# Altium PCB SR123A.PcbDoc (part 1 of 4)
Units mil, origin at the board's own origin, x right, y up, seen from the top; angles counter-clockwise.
Board outline 5500 x 3200 mil, 4 copper layers (Top Layer, Signal Layer 1, Signal Layer 2, Bottom Layer), stack 64.312 mil thick; 295 components, 105 nets, 659 pads, 1365 vias.
Unrouted connection lines stored in the file: 735.
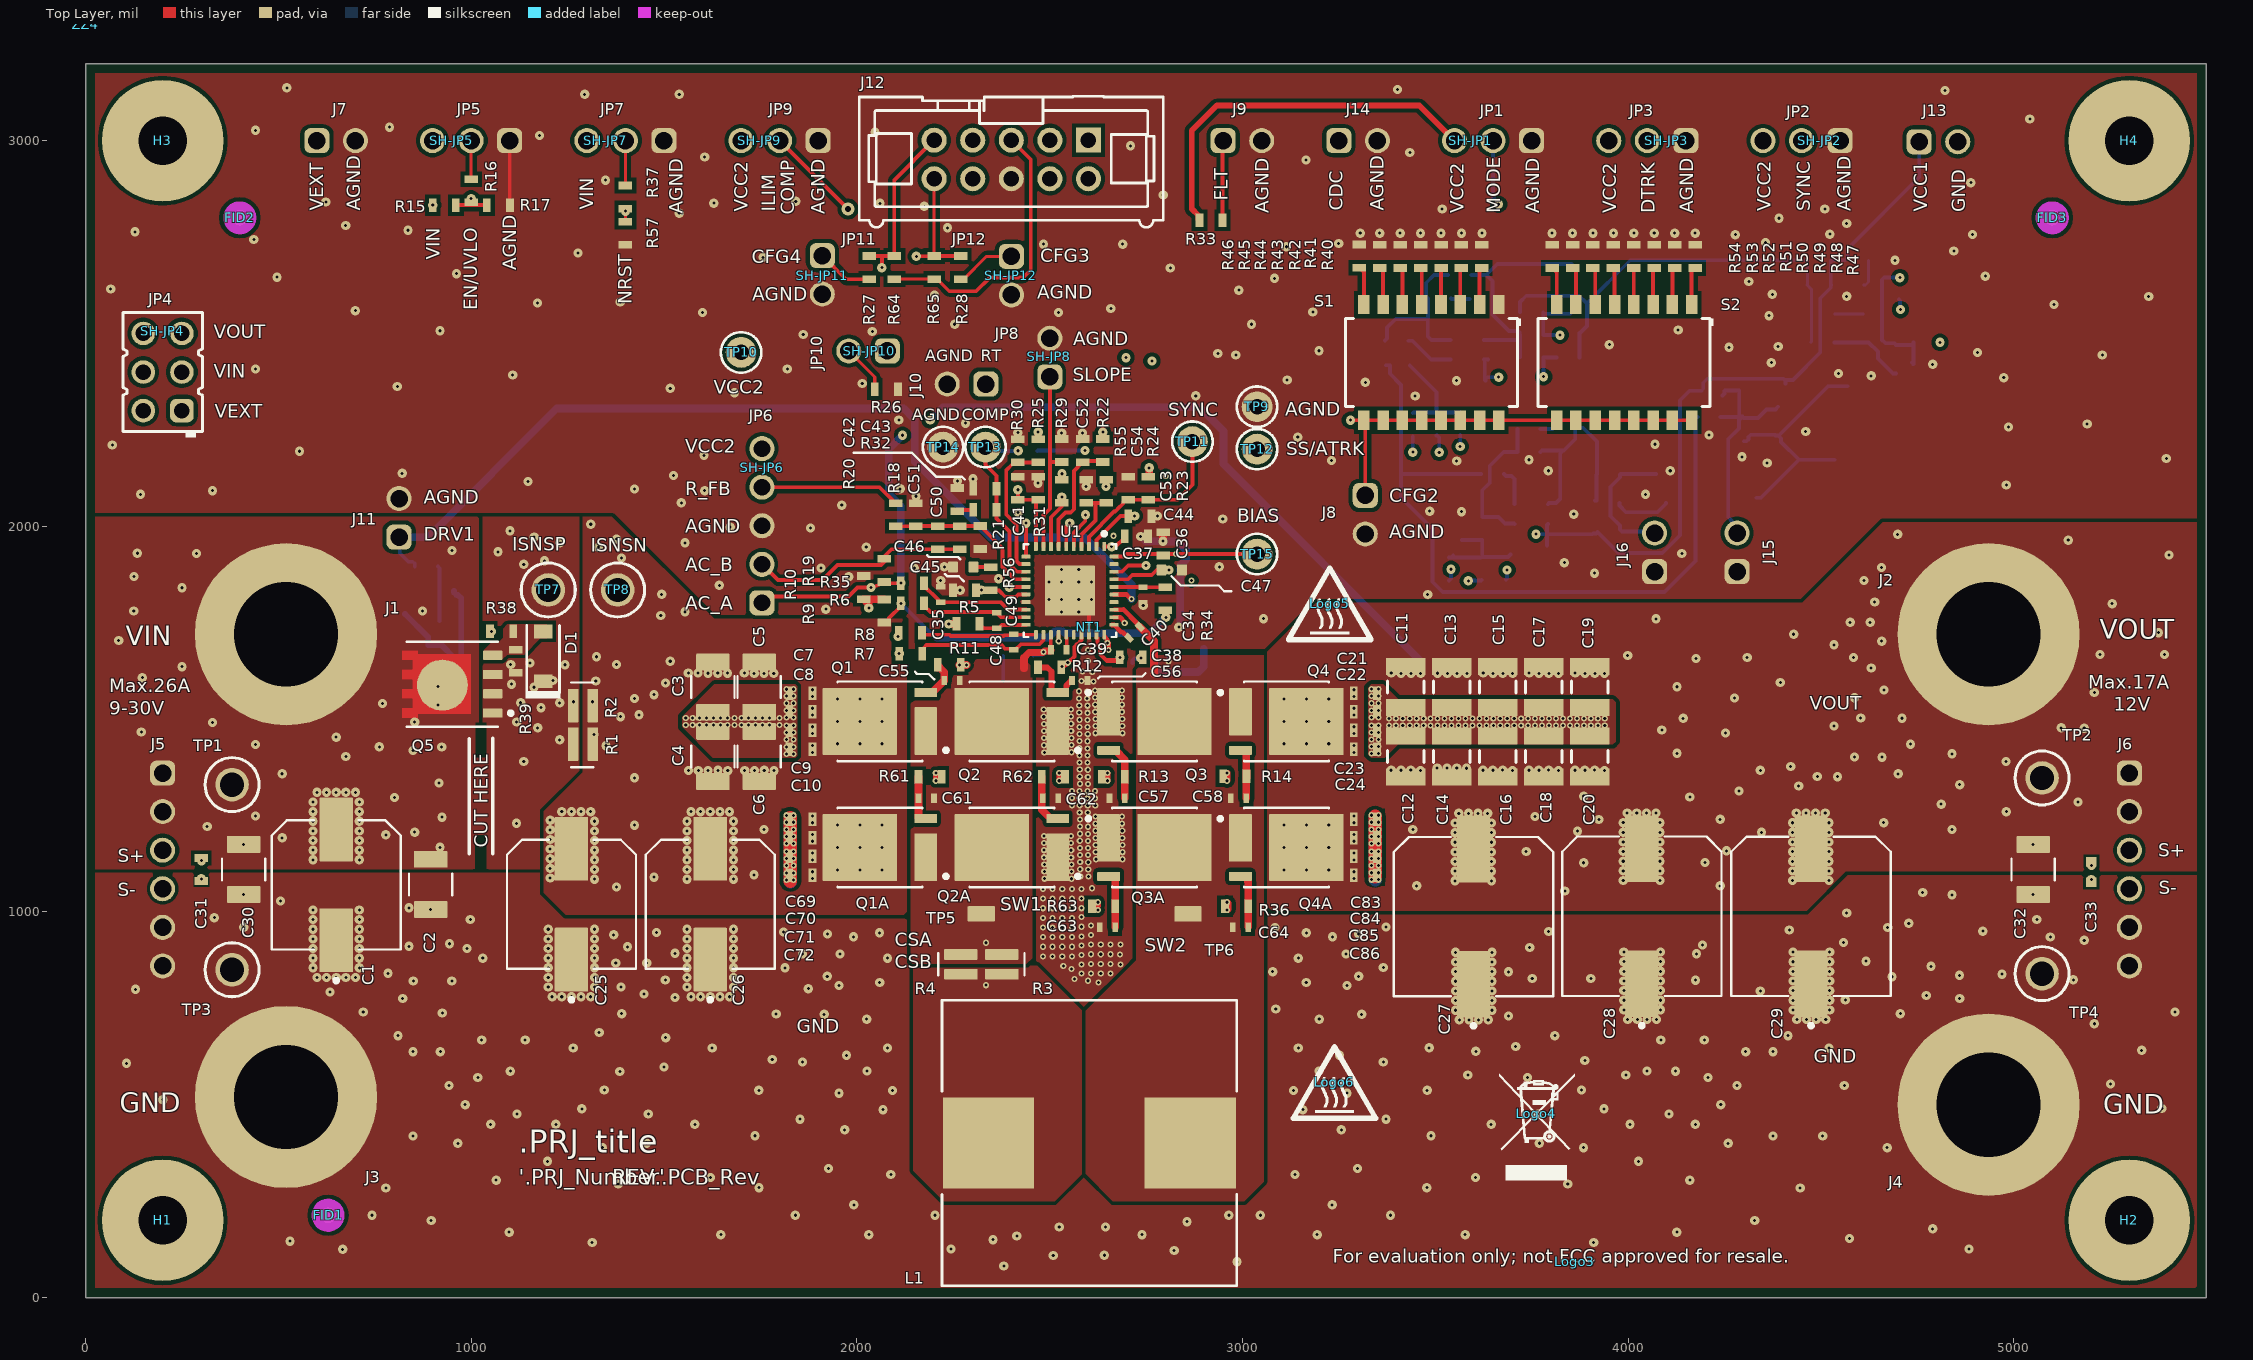
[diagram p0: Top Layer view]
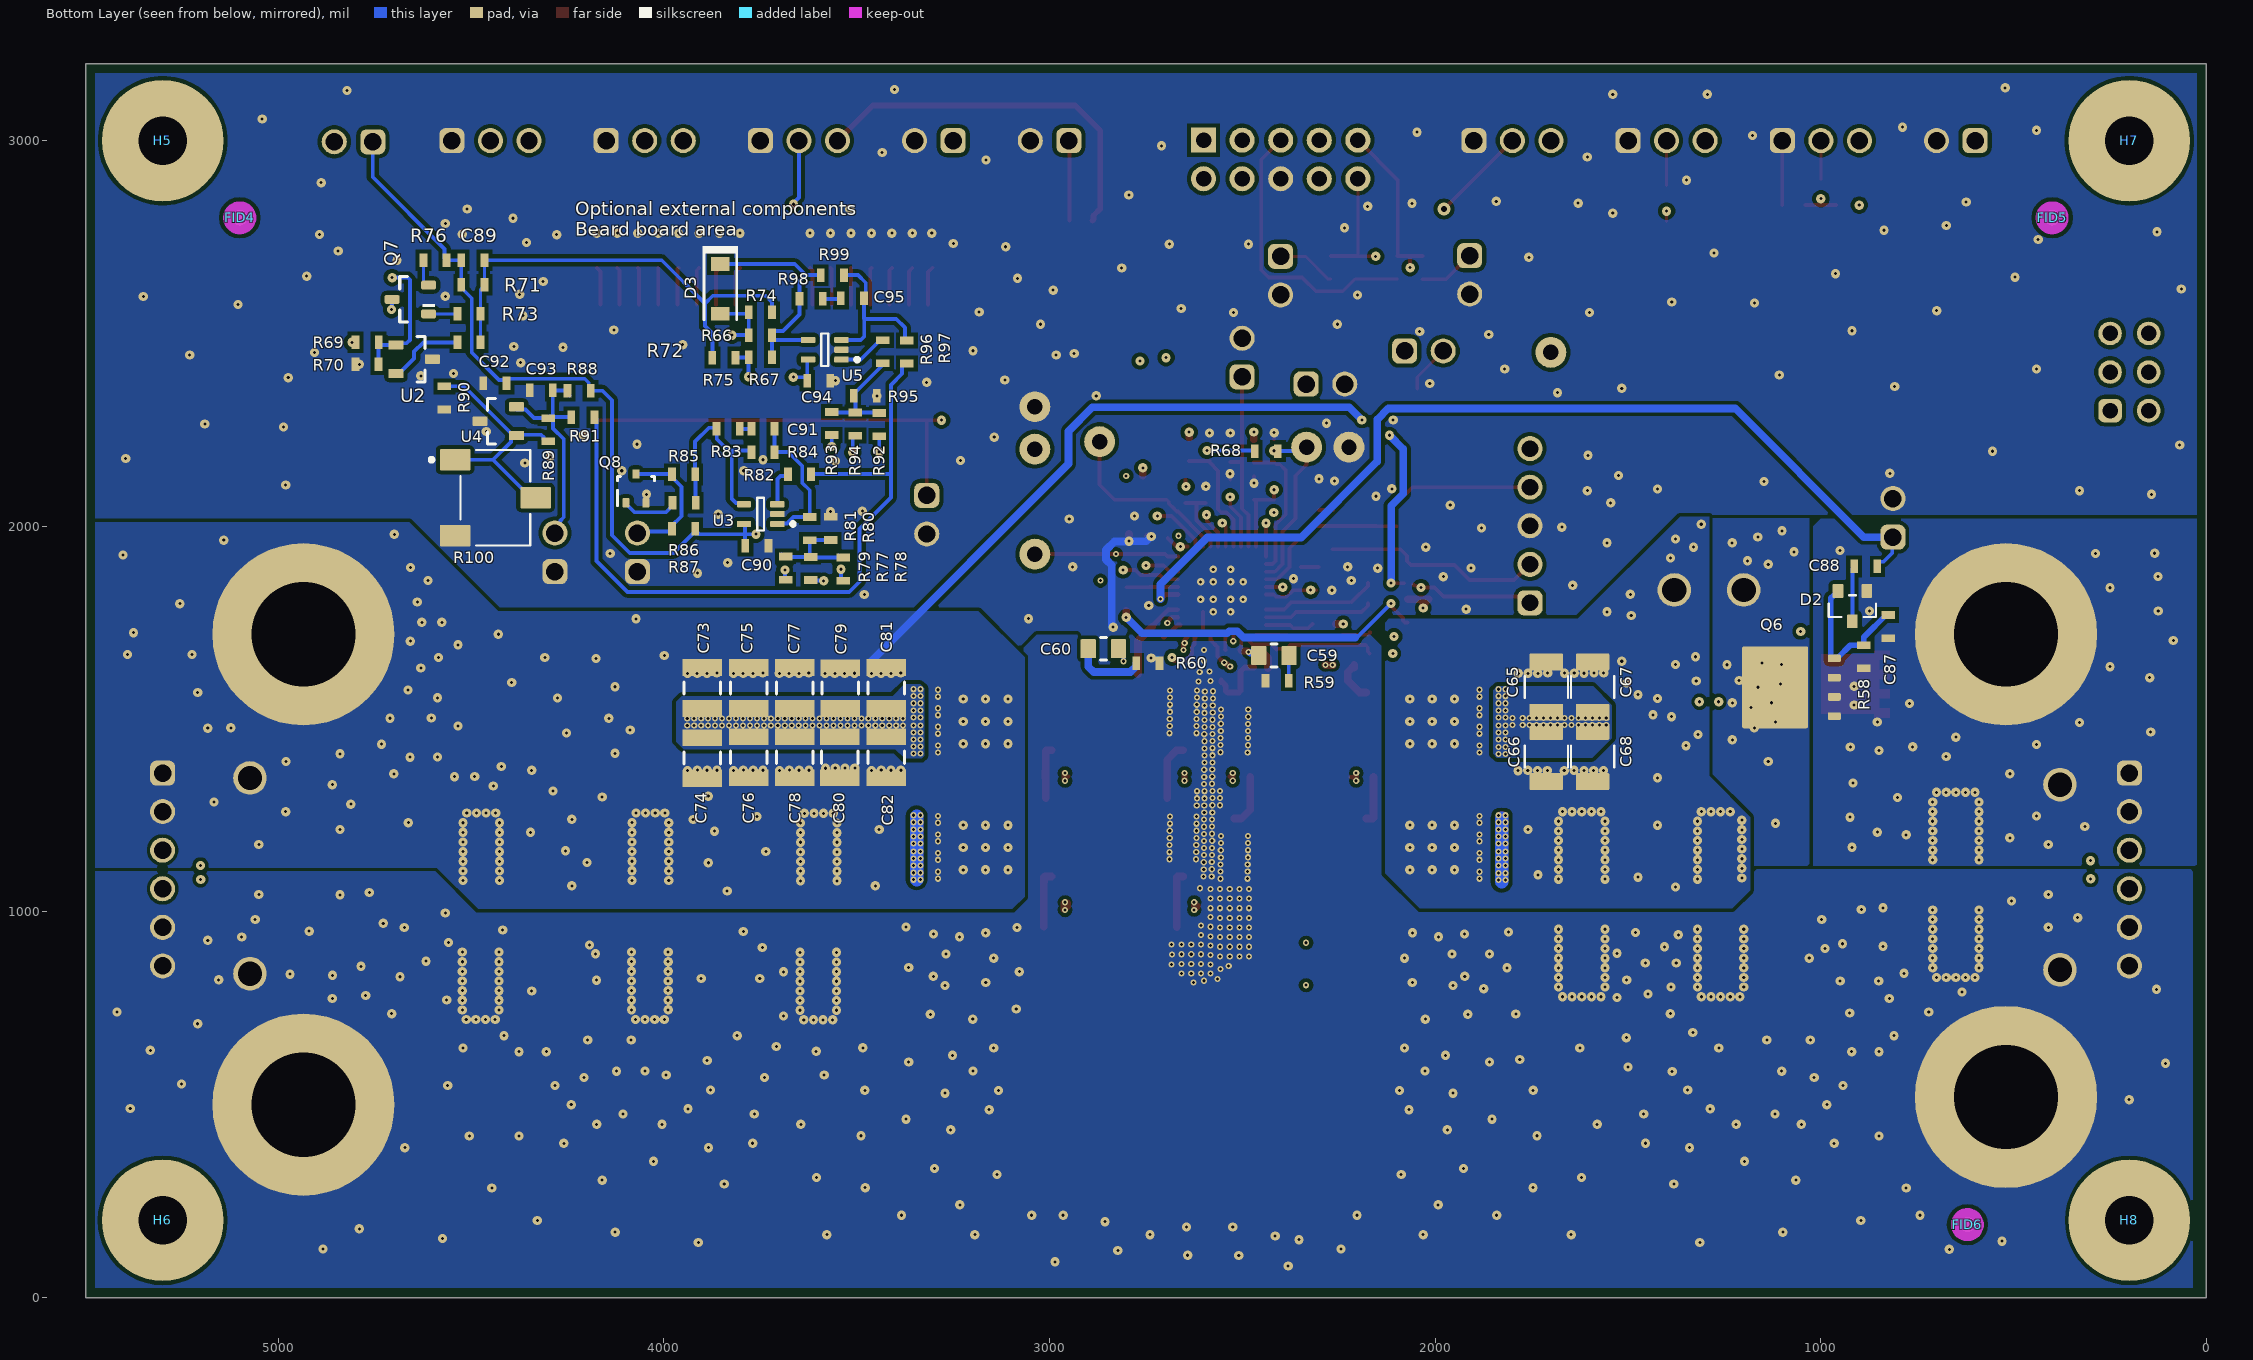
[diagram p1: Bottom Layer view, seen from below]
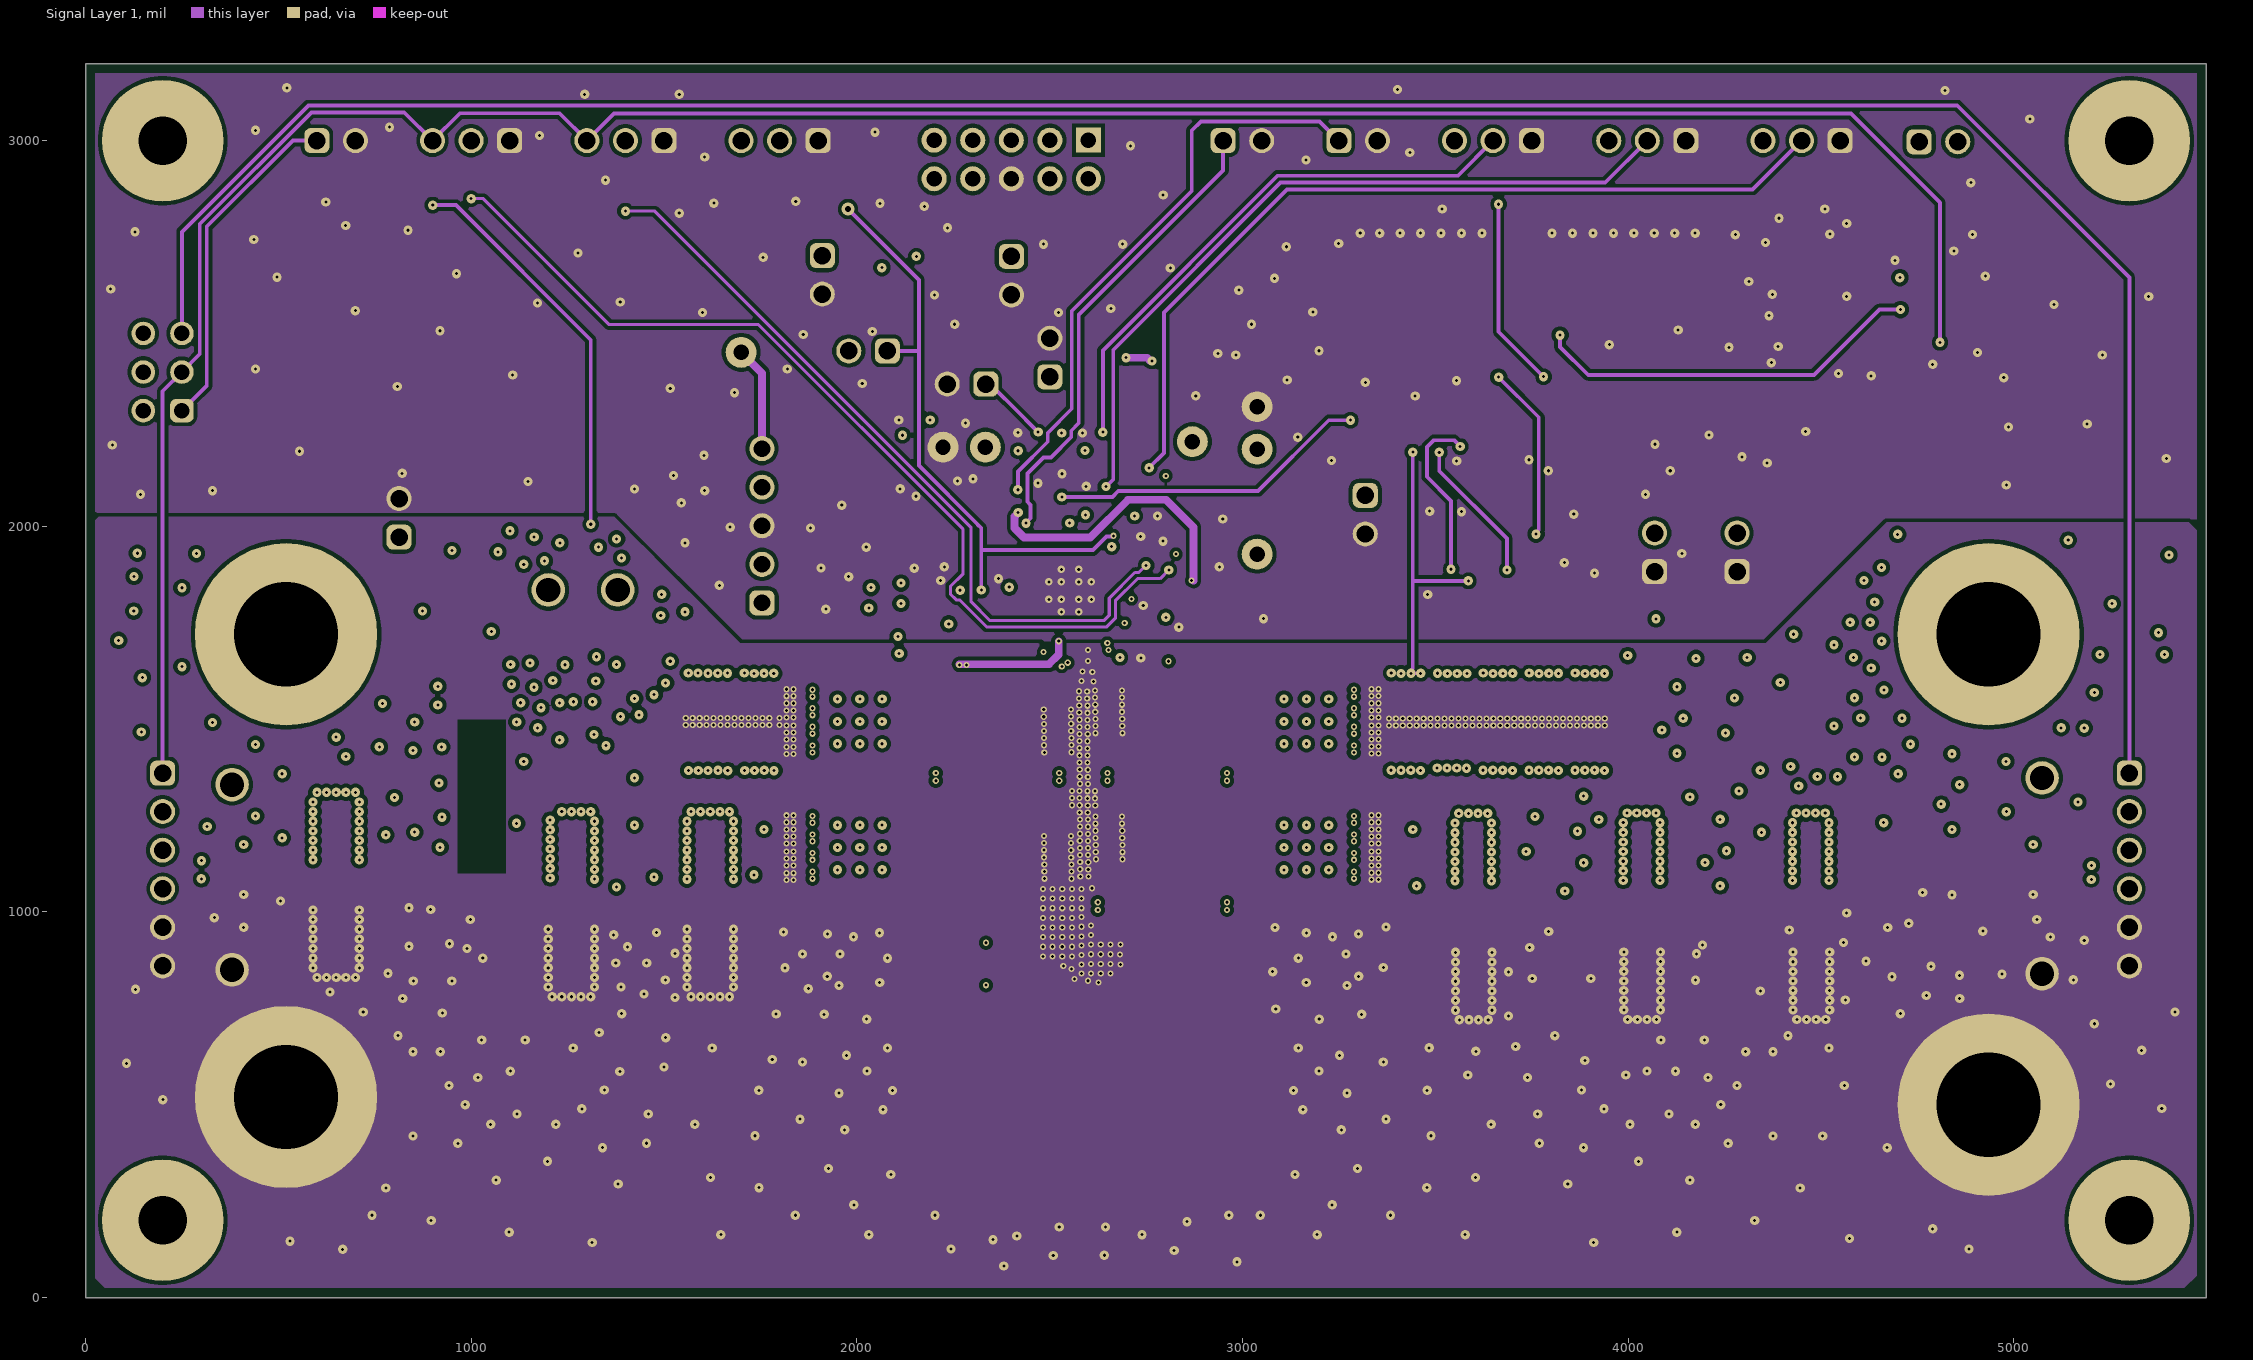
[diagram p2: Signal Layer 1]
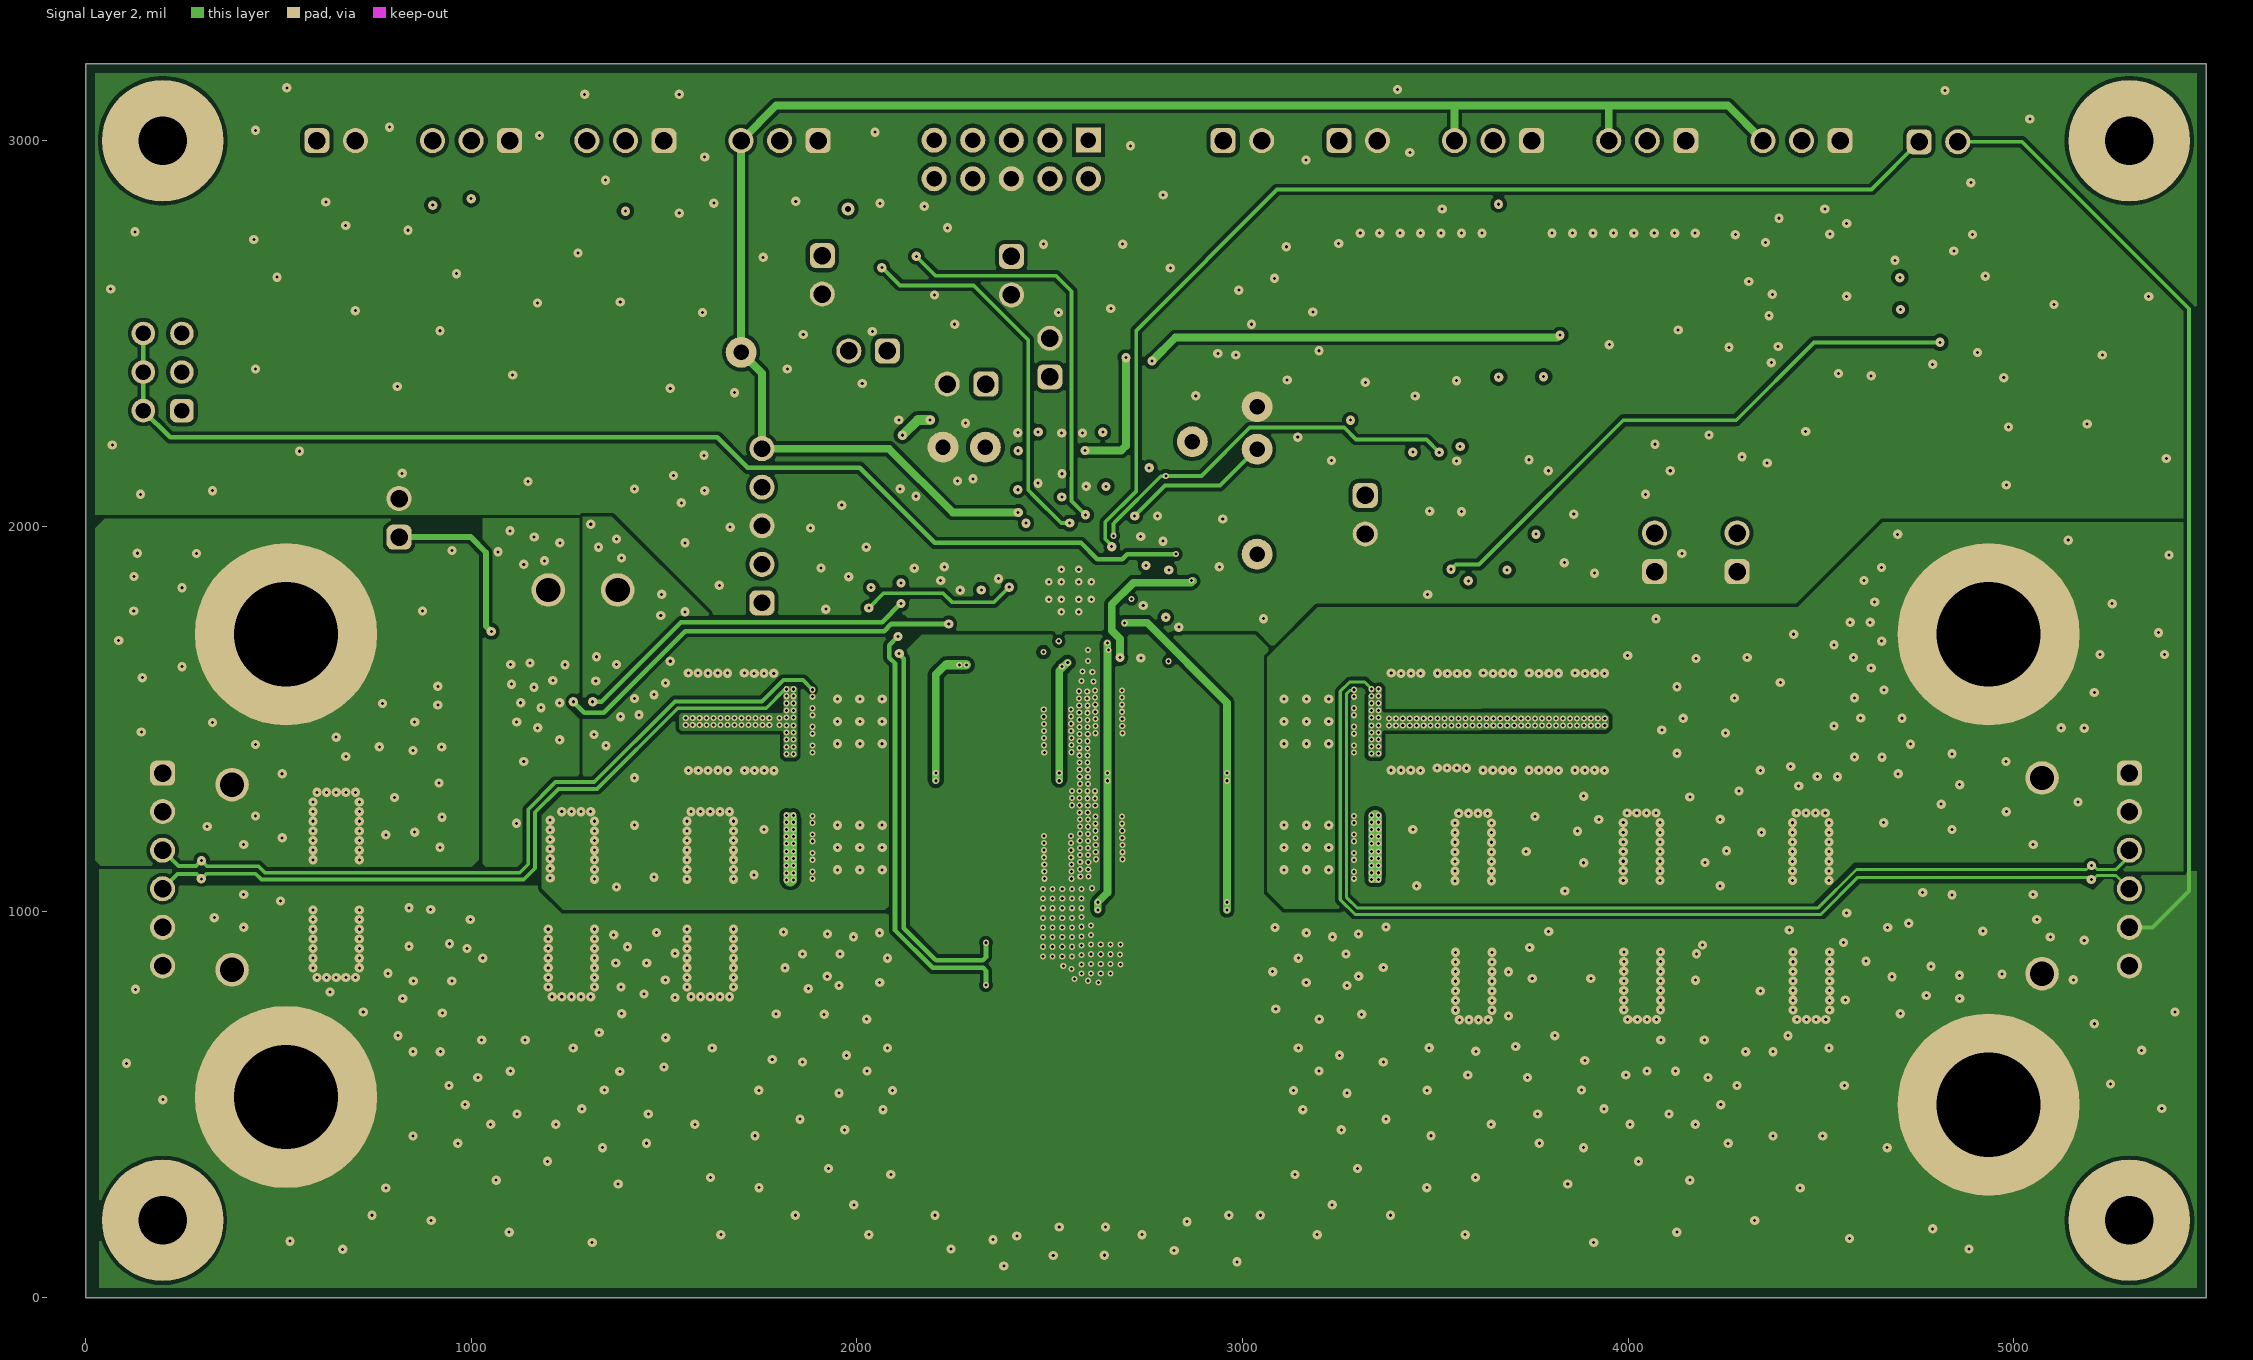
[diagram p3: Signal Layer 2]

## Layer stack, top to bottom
Top Solder: solder mask 0.4, Solder Resist, Dk 3.5
Top Layer: signal copper 2.8
Dielectric 1: prepreg 8, FR-4 High Tg, Dk 4.2
Signal Layer 1: signal copper 2.7559
Dielectric 2: core 37.2, FR-4 High Tg, Dk 4.2
Signal Layer 2: signal copper 2.7559
Dielectric 3: prepreg 8, FR-4 High Tg, Dk 4.2
Bottom Layer: signal copper 2.8
Bottom Solder: solder mask 0.4, Solder Resist, Dk 3.5

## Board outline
5500,0 5500,3200 0,3200 0,0

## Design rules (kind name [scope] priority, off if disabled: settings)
AcuteAngle [All] p1: minimum=4.50000000000000E+0001 checktracksonly=TRUE
AssemblyTestPointUsage [All] p1: valid=2
BoardOutlineClearance BoardOutlineClearance_MountingHoles [OnCopper and InComponentClass('Mounting Holes')] p1: gap=39.37 ignorepadtopadclearanceinfootprint=FALSE
BoardOutlineClearance BoardOutlineClearance_Poly [OnCopper and IsPoly] p2: gap=25 ignorepadtopadclearanceinfootprint=FALSE
BoardOutlineClearance [OnCopper and Not InComponentClass('Logo') and not InComponentClass('FiducialMark') and not InRegion(1000,500,4000,800) and not InPoly] p3: gap=40 ignorepadtopadclearanceinfootprint=FALSE
Clearance Clearance_Keepouts [((IsTrack Or IsArc) And Not InPoly) And IsFree and IsKeepOut vs ((IsTrack Or IsArc) And Not InPoly) And IsFree and IsKeepOut] p1: gap=0 ignorepadtopadclearanceinfootprint=FALSE
Clearance Clearance_Poly [InPolygon] p2: gap=10 ignorepadtopadclearanceinfootprint=TRUE
Clearance Clearance_FiducialMark [IsKeepOut and InComponentClass('FiducialMark') vs IsPad and InComponentClass('FiducialMark')] p3: gap=0 ignorepadtopadclearanceinfootprint=FALSE
Clearance [All] p4: gap=7.87 ignorepadtopadclearanceinfootprint=TRUE
ComponentClearance ComponentClearance_TP [InComponent('TP15')or InComponent('TP16')or InComponent('TP17')or InComponent('TP18')or InComponent('TP23')or InComponent('TP24')or InComponent('TP12')or InComponent('TP13')or InComponent('TP21')or InComponent('TP22') or InComponent('R100')] p1: gap=10 collisioncheckmode=3 verticalgap=0 showdistances=FALSE
ComponentClearance ComponentClearance_NT [InComponent('NT1') or InComponent('NT2')] p2: gap=-1 collisioncheckmode=3 verticalgap=0 showdistances=FALSE
ComponentClearance ComponentClearance_MountingHoles_FiducialMarks [InComponentClass('Mounting Holes') vs InComponentClass('FiducialMark')] p3: gap=50 collisioncheckmode=3 verticalgap=10 showdistances=FALSE
ComponentClearance ComponentClearance_Shunt [InComponentClass('Header') vs InComponent('SH-JP1') or InComponent('SH-JP2') or InComponent('SH-JP3') or InComponent('SH-JP4') or InComponent('SH-JP5') or InComponent('SH-JP6') or InComponent('SH-JP7') or InComponent('SH-JP8') or InComponent('SH-JP9') or InComponent('SH-JP10') or InComponent('SH-JP11') or InComponent('SH-JP12')] p4: gap=-1 collisioncheckmode=3 verticalgap=0 showdistances=FALSE
ComponentClearance ComponentClearance_Logo [InComponentClass('Logo')] p5: gap=20 collisioncheckmode=3 verticalgap=10 showdistances=FALSE
ComponentClearance ComponentClearance_ScrewToNut [(HasFootprint('NY PMS 440 0025 PH')) vs (HasFootprint('Keystone_1902C'))] p6: gap=5 collisioncheckmode=3 verticalgap=10 showdistances=FALSE
ComponentClearance ComponentClearance_MountingHoles [InComponentClass('Mounting Holes')] p7: gap=100 collisioncheckmode=3 verticalgap=100000 showdistances=FALSE
ComponentClearance ComponentClearance_SmallPassives [HasFootprint('0201*') or HasFootprint('0402*') or HasFootprint('0508') or HasFootprint('0603*') or HasFootprint('0612') or HasFootprint('0805*') or HasFootprint('0815*') or HasFootprint('0830*') or HasFootprint('1206*') or HasFootprint('1210*') or HasFootprint('1808*') or HasFootprint('1812*') or HasFootprint('1825*') or HasFootprint('2010*') or HasFootprint('2220*') or HasFootprint('2225*') or HasFootprint('2512*') or HasFootprint('2728*') or HasFootprint('3518*') vs HasFootprint('0201*') or HasFootprint('0402*') or HasFootprint('0508') or HasFootprint('0603*') or HasFootprint('0612') or HasFootprint('0805*') or HasFootprint('0815*') or HasFootprint('0830*') or HasFootprint('1206*') or HasFootprint('1210*') or HasFootprint('1808*') or HasFootprint('1812*') or HasFootprint('1825*') or HasFootprint('2010*') or HasFootprint('2220*') or HasFootprint('2225*') or HasFootprint('2512*') or HasFootprint('2728*') or HasFootprint('3518*')] p8: gap=10 collisioncheckmode=3 verticalgap=10 showdistances=FALSE
ComponentClearance ComponentClearance_THtoSMT [IsThruComponent vs IsSMTComponent] p9: gap=30 collisioncheckmode=3 verticalgap=30 showdistances=FALSE
ComponentClearance ComponentClearance_THtoTH [IsThruComponent vs IsThruComponent] p10: gap=20 collisioncheckmode=3 verticalgap=30 showdistances=FALSE
DiffPairsRouting [All] p1: maxlimit=100 minlimit=10 mostfreqgap=10 toplayer_minwidth=15 toplayer_maxwidth=15 toplayer_prefwidth=15 midlayer1_minwidth=15 midlayer1_maxwidth=15 midlayer1_prefwidth=15 midlayer2_minwidth=15 midlayer2_maxwidth=15 midlayer2_prefwidth=15 bottomlayer_minwidth=15 bottomlayer_maxwidth=15 bottomlayer_prefwidth=15 maxuncoupledlength=1000
FabricationTestPointUsage TestPointUsage [All] p1: valid=2 allowmultiple=FALSE
FabricationTestpoint Testpoint [All] p1: side=3 testpointundercomponent=TRUE minsize=40 maxsize=100 preferedsize=60 minholesize=0 maxholesize=40 preferedholesize=32 testpointgrid=1 allowsidetop=TRUE allowsidebottom=TRUE usegrid=TRUE gridtolerance=0.01
FanoutControl Fanout_LCC [IsLCC] p1: bgadir=Out bgaviamode=Centered fanoutstyle=Auto fanoutdirection=Alternating viagrid=1 // Fanout_LCC (Default Rule)
FanoutControl Fanout_BGA [IsBGA] p2: bgadir=Out bgaviamode=Centered fanoutstyle=Auto fanoutdirection=Alternating viagrid=1 // Fanout_BGA (Default Rule)
FanoutControl Fanout_Default [All] p4: bgadir=Out bgaviamode=Centered fanoutstyle=Auto fanoutdirection=Alternating viagrid=1 // Fanout_Default (Default Rule)
FanoutControl Fanout_Small [(CompPinCount < 5)] p5: bgadir=Out bgaviamode=Centered fanoutstyle=Auto fanoutdirection=OutThenIn viagrid=1 // Fanout_Small (Default Rule)
HoleSize [All] p1: absolutevalues=TRUE maxlimit=275 minlimit=7.87 maxpercent=80.000 minpercent=20.000
MinimumAnnularRing MinimumAnnularRing_QFN_Room [WithinRoom('QFN_Room')] p1: minimumring=5.9
MinimumAnnularRing MinimumAnnularRing_ThermalPadVias [IsVia and InAnyComponent] p2: minimumring=5.91
MinimumAnnularRing [All] p3: minimumring=4
MinimumSolderMaskSliver MinimumSolderMaskSliver_Logo [InComponentClass('Logo') vs InComponentClass('Logo')] p1: minsoldermaskwidth=0.7
MinimumSolderMaskSliver [All] p2: minsoldermaskwidth=3.94
PlaneConnect [All] p1: planeconnectstyle=Relief reliefexpansion=10 reliefentries=4 reliefconductorwidth=10 reliefairgap=10
PolygonConnect [All] p1: connectstyle=Direct reliefconductorwidth=10 reliefentries=4 polygonreliefangle="90 Angle" airgapwidth=10
RoomDefinition QFN_Room [False] p1: confinementstyle=ConfineIn formatcopy=TRUE lockcomponents=FALSE outline 2447.29,1945.95 2657.01,1945.95 2657.01,1733.12 2447.29,1733.12
RoutingVias RoutingVias_QFN_Room [WithinRoom('QFN_Room')] p1: holewidth=28 width=50 viastyle="Through Hole" minholewidth=7.87 minwidth=19.68 maxholewidth=28 maxwidth=50
RoutingVias ThermalPadVias [IsVia and InAnyComponent] p2: holewidth=7.87 width=19.68 viastyle="Through Hole" minholewidth=7.87 minwidth=19.68 maxholewidth=12.99 maxwidth=23.62
RoutingVias [All] p3: holewidth=16 width=34 viastyle="Through Hole" minholewidth=7.87 minwidth=16 maxholewidth=40 maxwidth=65
SilkToBoardRegionClearance [Not ((IsComment or IsDesignator) And (Hide <> 'False')) and not InRegion(1000,500,4000,800)] p1:
SilkToSilkClearance SilkToSilkClearance_Pb-FreeLogo [(HasFootprint('Pb-Free_Overlay_Medium') OR HasFootprint('Pb-Free_Overlay_Small')) vs (HasFootprint('Pb-Free_Overlay_Medium') OR HasFootprint('Pb-Free_Overlay_Small'))] p1: silktosilkclearance=0
SilkToSilkClearance [All] p2: silktosilkclearance=3.94
SilkToSolderMaskClearance SilkToComponentPadClearance [(IsPad or IsFill or IsRegion) and InAnycomponent] p1: minsilkscreentomaskgap=5 clearancetoexposedcopper=TRUE
SilkToSolderMaskClearance "Silk to Solder Mask Opening" [All] p2: minsilkscreentomaskgap=3.94 clearancetoexposedcopper=FALSE
SolderMaskExpansion [All] p1: expansion=1.97 istentingtop=FALSE
SupplyNets "Schematic Supply Nets_3" [InNet('GND')] p1: voltage=0.000
SupplyNets "Schematic Supply Nets_2" [InNet('AGND')] p2: voltage=0.000
SupplyNets "Schematic Supply Nets_1" [InNet('VCC1')] p3: voltage=0.000
SupplyNets "Schematic Supply Nets" [InNet('VBUS')] p4: voltage=0.000
UnRoutedNet [All] p1: checkbadconnections=TRUE
Width [All] p1: maxlimit=100 minlimit=6 preferedwidth=10
14 further rules are at their usual default settings.

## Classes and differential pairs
component class SR123A_OptExtLogic: C89 C90 C91 C92 C93 C94 C95 D3 J15 J16 Q7 Q8 R66 R67 R68 R69 R70 R71 R72 R73 R74 R75 R76 R77 R78 R79 R80 R81 R82 R83 R84 R85 R86 R87 R88 R89 R90 R91 R92 R93 R94 R95 R96 R97 R98 R99 R100 U2 U3 U4 U5
component class Header: J5 J6 J7 J8 J9 J10 J11 J13 J14 J15 J16 JP1 JP2 JP3 JP4 JP5 JP6 JP7 JP8 JP9 JP10 JP11 JP12
component class SR123A: 6 C1 C2 C3 C4 C5 C6 C7 C8 C9 C10 C11 C12 C13 C14 C15 C16 C17 C18 C19 C20 C21 C22 C23 C24 C25 C26 C27 C28 C29 C30 C31 C32 C33 C34 C35 C36 C37 C38 C39 C40 C41 C42 C43 C44 C45 C46 C47 C48 C49 C50 C51 C52 C53 C54 C55 C56 C57 C58 C59 C60 C61 C62 C63 C64 C65 C66 C67 C68 C69 C70 C71 C72 C73 C74 C75 C76 C77 C78 C79 C80 C81 C82 C83 C84 C85 C86 C87 C88 D1 D2 J1 J2 J3 J4 J5 J6 J7 J8 J9 J10 J11 J12 J13 J14 JP1 JP2 JP3 JP4 JP5 JP6 JP7 JP8 JP9 JP10 JP11 JP12 L1 NT1 Q1 Q1A Q2 Q2A Q3 Q3A Q4 Q4A Q5 Q6 R1 R2 R3 R4 R5 R6 R7 R8 R9 R10 R11 R12 R13 R14 R15 R16 R17 R18 R19 R20 R21 R22 R23 R24 R25 R26 R27 R28 R29 R30 R31 R32 R33 R34 R35 R36 R37 R38 R39 R40 R41 R42 R43 R44 R45 R46 R47 R48 R49 R50 R51 R52 R53 R54 R55 R56 R57 R58 R59 R60 R61 R62 R63 R64 R65 R301 R302 S1 S2 TP1 TP2 TP3 TP4 TP5 TP6 TP7 TP8 TP9 TP10 TP11 TP12 TP13 TP14 TP15 U1
component class "Mounting Holes": H1 H2 H3 H4
component class SR123A_Hardware: FID1 FID2 FID3 FID4 FID5 FID6 H1 H2 H3 H4 H5 H6 H7 H8 Logo3 Logo4 Logo5 Logo6 SH-JP1 SH-JP2 SH-JP3 SH-JP4 SH-JP5 SH-JP6 SH-JP7 SH-JP8 SH-JP9 SH-JP10 SH-JP11 SH-JP12 ZZ2 ZZ3 ZZ4
component class FiducialMark: FID1 FID2 FID3 FID4 FID5 FID6
component class AssemblyNote: ZZ2 ZZ3 ZZ4

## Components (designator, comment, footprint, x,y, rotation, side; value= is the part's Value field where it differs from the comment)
C1 "A768KE276M1JLAE054" FP-A768KE276M1JLAE054_SMT_CAP_8MM3_8MM3-0 650,1070 r90 top locked value=27µF
C2 "C3225X7R2A106K250AC" FP-C3225X7R2A106K250AC_1210-MFG 895,1071.23 r90 top locked value=10µF
C3 "C3225X7R2A106K250AC" FP-C3225X7R2A106K250AC_1210-MFG 1627,1583 r270 top value=10µF
C4 "C3225X7R2A106K250AC" FP-C3225X7R2A106K250AC_1210-MFG 1627,1403 r90 top value=10µF
C5 "C3225X7R2A106K250AC" FP-C3225X7R2A106K250AC_1210-MFG 1747,1583 r270 top value=10µF
C6 "C3225X7R2A106K250AC" FP-C3225X7R2A106K250AC_1210-MFG 1747,1403 r90 top value=10µF
C7 "GCJ188R72A104KA01D" 0603S 1855,1567 r180 top value=0.1uF
C8 "GCJ188R72A104KA01D" 0603S 1855,1519 r180 top value=0.1uF
C9 "GCJ188R72A104KA01D" 0603S 1855,1471 r180 top value=0.1uF
C10 "GCJ188R72A104KA01D" 0603S 1855,1422 r180 top value=0.1uF
C11 "GMK325BJ226MM-P" 1210L 3424,1583 r90 top value=22uF
C12 "GMK325BJ226MM-P" 1210L 3424,1403 r270 top value=22uF
C13 "GMK325BJ226MM-P" 1210L 3543.23,1583 r90 top value=22uF
C14 "GMK325BJ226MM-P" 1210L 3543.23,1403 r270 top value=22uF
C15 "GMK325BJ226MM-P" 1210L 3662.46,1583 r270 top value=22uF
C16 "GMK325BJ226MM-P" 1210L 3662.46,1403 r90 top value=22uF
C17 "GMK325BJ226MM-P" 1210L 3781.69,1583 r270 top value=22uF
C18 "GMK325BJ226MM-P" 1210L 3781.69,1403 r90 top value=22uF
C19 "GMK325BJ226MM-P" 1210L 3900.92,1583 r270 top value=22uF
C20 "GMK325BJ226MM-P" 1210L 3900.92,1403 r90 top value=22uF
C21 "GCJ188R72A104KA01D" 0603S 3319,1567 r0 top value=0.1uF
C22 "GCJ188R72A104KA01D" 0603S 3319,1519 r0 top value=0.1uF
C23 "GCJ188R72A104KA01D" 0603S 3319,1471 r0 top value=0.1uF
C24 "GCJ188R72A104KA01D" 0603S 3319,1422 r0 top value=0.1uF
C25 "A768KE276M1JLAE054" FP-A768KE276M1JLAE054_SMT_CAP_8MM3_8MM3-0 1260,1020 r90 top value=27µF
C26 "A768KE276M1JLAE054" FP-A768KE276M1JLAE054_SMT_CAP_8MM3_8MM3-0 1620,1020 r90 top value=27µF
C27 "A768MS127M1HLAE024" FP-A768MS127M1HLAE024_SMT_CAP_10MM3_10MM3-MFG 3599.27,987.81 r90 top value=120µF
C28 "A768MS127M1HLAE024" FP-A768MS127M1HLAE024_SMT_CAP_10MM3_10MM3-MFG 4035.91,988.7 r90 top value=120µF
C29 "A768MS127M1HLAE024" FP-A768MS127M1HLAE024_SMT_CAP_10MM3_10MM3-MFG 4474.55,988.49 r90 top value=120µF
C30 "C3225X7R2A106K250AC" FP-C3225X7R2A106K250AC_1210-MFG 410,1110 r90 top locked value=10µF
C31 "GCJ188R72A104KA01D" 0603S 300,1110 r270 top value=0.1uF
C32 "C3225X7R2A106K250AC" FP-C3225X7R2A106K250AC_1210-MFG 5050.72,1110 r90 top value=10µF
C33 "GCM188L81H104KA57D" FP-GCM188L81H104KA57D_0603-MFG 5201.43,1103.31 r270 top
C34 "GRM155R62A104KE14D" 0402S 2742.37,1821.95 r90 top value=0.1uF
C35 "GRM155R62A104KE14D" 0402S 2217.79,1823.16 r90 top value=0.1uF
C36 "CGA3E3X7S2A104K080AB" 0603S 2794.32,1954.37 r270 top value=0.1uF
C37 "GRT188R61A226ME13D" 0603S 2725.01,1974.28 r180 top value=22µF
C38 "GRT188R61A226ME13D" 0603S 2711.59,1660.19 r180 top value=22µF
C39 "GCM155R71H104KE02D" 0402S 2523.73,1679.54 r0 top value=0.1uF
C40 "GCM155R71H104KE02D" 0402S 2720,1725 r225 top value=0.1uF
C41 "06035A560FAT2A" 0603S 2417.93,2098.72 r90 top value=56pF
C42 "C0603X223K5RACTU" 0603S 2261.07,2069.11 r90 top value=0.022uF
C43 "06035A560JAT2A" 0603S 2332.19,2097.1 r180 top value=56pF
C44 "06035C333JAT2A" 0603S 2734.01,2026.62 r0 top value=0.033uF
C45 "CL10C330FB8NNNC" 0603S 2279.35,1834.12 r180 top value=33pF
C46 "GCM188L81H104KA57D" FP-GCM188L81H104KA57D_0603-MFG 2275.8,1894.43 r180 top
C47 "GCM188L81H104KA57D" FP-GCM188L81H104KA57D_0603-MFG 2816.62,1886.67 r0 top
C48 "GRM1555C1H101JA01D" 0402S 2407,1700 r270 top value=100pF
C49 "0402BB104KW500" 0402S 2362.79,1755.65 r270 top value=0.1uF
C50 "GRM1885C2A200JA01D" 0603S 2209.91,1970.42 r90 top value=20pF
C51 "GRM1885C1H151JA01D" 0603S 2153.05,2029.98 r90 top value=150pF
C52 "06031C102JAT2A" 0603S 2585.69,2196.38 r90 top value=1000pF
C53 "06031C102JAT2A" 0603S 2703.56,2098.72 r90 top value=1000pF
C54 "06031C102JAT2A" 0603S 2594.9,2090.8 r90 top value=1000pF
C55 "GCM1555C1H681FA16D" 0402S 2247.09,1600.2 r0 top value=680pF
C56 "GCM1555C1H681FA16D" 0402S 2578,1600 r0 top value=680pF
C57 "GCM1555C1H681FA16D" 0402S 2675,1295 r180 top value=680pF
C58 "GRM155R71H472KA01D" 0402S 2990,1295 r0 top value=4700pF
C59 "GRM2195C2A681JA01D" 0805_HV1 2418.2,1664.74 r0 bottom locked value=680pF
C60 "GRM2165C2A302JA01D" 0805_HV1 2860.32,1682.46 r180 bottom value=3000pF
C61 "GCM1555C1H681FA16D" 0402S 2180,1295 r0 top value=680pF
C62 "GCM1555C1H681FA16D" 0402S 2502.23,1295 r0 top value=680pF
C63 "GCM1555C1H681FA16D" 0402S 2650,960 r180 top value=680pF
C64 "GRM155R71H472KA01D" 0402S 2995,960 r0 top value=4700pF
C65 "C3225X7R2A106K250AC" FP-C3225X7R2A106K250AC_1210-MFG 1712,1583 r270 bottom value=10µF
C66 "C3225X7R2A106K250AC" FP-C3225X7R2A106K250AC_1210-MFG 1712,1403 r90 bottom value=10µF
C67 "C3225X7R2A106K250AC" FP-C3225X7R2A106K250AC_1210-MFG 1592,1583 r270 bottom value=10µF
C68 "C3225X7R2A106K250AC" FP-C3225X7R2A106K250AC_1210-MFG 1592,1403 r90 bottom value=10µF
C69 "GCJ188R72A104KA01D" 0603S 1855,1240 r180 top value=0.1uF
C70 "GCJ188R72A104KA01D" 0603S 1855,1192 r180 top value=0.1uF
C71 "GCJ188R72A104KA01D" 0603S 1855,1144 r180 top value=0.1uF
C72 "GCJ188R72A104KA01D" 0603S 1855,1095 r180 top value=0.1uF
C73 "GMK325BJ226MM-P" 1210L 3900.5,1580.79 r90 bottom value=22uF
C74 "GMK325BJ226MM-P" 1210L 3900.5,1398.85 r270 bottom value=22uF
C75 "GMK325BJ226MM-P" 1210L 3780.5,1580.79 r90 bottom value=22uF
C76 "GMK325BJ226MM-P" 1210L 3780.5,1400.85 r270 bottom value=22uF
C77 "GMK325BJ226MM-P" 1210L 3660.5,1580.79 r270 bottom value=22uF
C78 "GMK325BJ226MM-P" 1210L 3660.5,1400.85 r270 bottom value=22uF
C79 "GMK325BJ226MM-P" 1210L 3543.1,1580.36 r270 bottom value=22uF
C80 "GMK325BJ226MM-P" 1210L 3543.82,1400.85 r90 bottom value=22uF
C81 "GMK325BJ226MM-P" 1210L 3423.82,1580.85 r90 bottom value=22uF
C82 "GMK325BJ226MM-P" 1210L 3423.82,1400.85 r90 bottom value=22uF
C83 "GCJ188R72A104KA01D" 0603S 3319,1240 r180 top value=0.1uF
C84 "GCJ188R72A104KA01D" 0603S 3319,1192 r180 top value=0.1uF
C85 "GCJ188R72A104KA01D" 0603S 3319,1144 r180 top value=0.1uF
C86 "GCJ188R72A104KA01D" 0603S 3319,1095 r180 top value=0.1uF
C87 "GCJ188R72A104KA01D" 0603S 825.67,1739.79 r270 bottom value=0.1uF
C88 "GCJ188R72A104KA01D" 0603S 883.6,1895.71 r0 bottom value=0.1uF
C89 "C0603C183K1RACTU" 0603S 4495.53,2689.74 r180 bottom value=0.018uF
C90 "C0603X104K3RACTU" 0603S 3759.03,1949.5 r180 bottom value=0.1uF
C91 "C0603C183K1RACTU" 0603S 3743.14,2252.71 r0 bottom value=0.018uF
C92 "C0603X104K3RACTU" 0603S 4438.53,2370.5 r0 bottom value=0.1uF
C93 "GRM188R61A106KE69D" 0603S 4318.22,2352.12 r0 bottom value=10uF
C94 "C0603X104K3RACTU" 0603S 3598.53,2377.5 r180 bottom value=0.1uF
C95 "C0603C183K1RACTU" 0603S 3511.23,2590.74 r0 bottom value=0.018uF
D1 "MMSZ4697T1G" SOD-123 1186.34,1662.72 r90 top value=10V
D2 "BAS70-04-E3-18" FP-BAS70-04-E3-18_SOT23-3-MFG 918.17,1792.94 r270 bottom
D3 "BAT54T1G" SOD-123 3853.53,2615.5 r270 bottom value=30V
FID1 "Fiducial" Fiducial10-20 629.1,213.39 r0 top
FID2 "Fiducial" Fiducial10-20 400,2800 r0 top
FID3 "Fiducial" Fiducial10-20 5100,2800 r0 top
FID4 "Fiducial" Fiducial10-20 5100,2800 r180 bottom
FID5 "Fiducial" Fiducial10-20 400,2800 r180 bottom
FID6 "Fiducial" Fiducial10-20 620,189.02 r180 bottom
H1 "NY PMS 440 0025 PH" "NY PMS 440 0025 PH" 200,200 r0 top
H2 "NY PMS 440 0025 PH" "NY PMS 440 0025 PH" 5300,200 r0 top
H3 "NY PMS 440 0025 PH" "NY PMS 440 0025 PH" 200,3000 r0 top locked
H4 "NY PMS 440 0025 PH" "NY PMS 440 0025 PH" 5300,3000 r0 top
H5 "1902C" Keystone_1902C 5300,3000 r180 bottom locked
H6 "1902C" Keystone_1902C 5300,200 r180 bottom
H7 "1902C" Keystone_1902C 200,3000 r180 bottom locked
H8 "1902C" Keystone_1902C 200,200 r180 bottom locked
J1 "108-0740-001" Johnson_108-0740-001 520,1720 r0 top
J2 "108-0740-001" Johnson_108-0740-001 4935,1720 r0 top
J3 "108-0740-001" Johnson_108-0740-001 520,520 r0 top
J4 "108-0740-001" Johnson_108-0740-001 4935,500 r0 top
J5 "61300611121" WURTH_61300611121 200,1110 r270 top
J6 "61300611121" WURTH_61300611121 5300,1110 r270 top
J7 "61300211121" WURTH_61300211121 650,3000 r0 top
J8 "61300211121" WURTH_61300211121 3318.61,2030 r270 top
J9 "61300211121" WURTH_61300211121 3000,3000 r0 top
J10 "61300211121" WURTH_61300211121 2284.52,2368.9 r180 top
J11 "61300211121" WURTH_61300211121 813,2021.92 r90 top
J12 "N2510-6002-RB" CONN_2510-6002 2400.67,2951.23 r180 top
J13 "61300211121" WURTH_61300211121 4805,2997 r0 top
J14 "61300211121" WURTH_61300211121 3300,3000 r0 top
J15 "61300211121" WURTH_61300211121 4282.86,1932.51 r90 top
J16 "61300211121" WURTH_61300211121 4068.96,1932.51 r90 top
JP1 "61300311121" WURTH_61300311121 3650,3000 r180 top
JP2 "61300311121" WURTH_61300311121 4450,3000 r180 top
JP3 "61300311121" WURTH_61300311121 4050,3000 r180 top
JP4 "HTSW-103-07-G-D" Samtec_HTSW-103-07-x-D 200,2400 r180 top
JP5 "61300311121" WURTH_61300311121 1000,3000 r180 top
JP6 "61300511121" Wurth_61300511121 1754.31,2001.32 r90 top
JP7 "61300311121" WURTH_61300311121 1400,3000 r180 top
JP8 "61300211121" WURTH_61300211121 2500.64,2437.56 r90 top
JP9 "61300311121" WURTH_61300311121 1800,3000 r180 top
JP10 "61300211121" WURTH_61300211121 2029.27,2454.69 r180 top
JP11 "61300211121" WURTH_61300211121 1910.65,2652 r270 top
JP12 "61300211121" WURTH_61300211121 2401.09,2649.94 r270 top
L1 "7443556260" WE-HCB_1890 2602.98,401 r0 top value=2.6uH
Logo3 "FCC disclaimer" FCC_disclaimer 3861.23,92.72 r0 top
Logo4 "WEEE logo" WEEE_Minimum 3761.84,476.02 r0 top
Logo5 "CAUTION HOT SURFACE" IEC_HotSurface_Small 3226.56,1798.94 r0 top
Logo6 "CAUTION HOT SURFACE" IEC_HotSurface_Small 3238.77,557.87 r0 top
NT1 "Net-Tie" Net-Tie_10mil 2602.22,1738.34 r90 top net-tie
Q1 "IAUCN04S7L014ATMA1" FP-IAUCN04S7L014ATMA1_TDSON8-MFG 2060,1494 r90 top
Q1A "IAUCN04S7L014ATMA1" FP-IAUCN04S7L014ATMA1_TDSON8-MFG 2060,1167 r90 top
Q2 "IAUCN04S7L014ATMA1" FP-IAUCN04S7L014ATMA1_TDSON8-MFG 2402,1494 r90 top
Q2A "IAUCN04S7L014ATMA1" FP-IAUCN04S7L014ATMA1_TDSON8-MFG 2402,1167 r90 top
Q3 "IAUCN04S7L014ATMA1" FP-IAUCN04S7L014ATMA1_TDSON8-MFG 2772,1494 r270 top
Q3A "IAUCN04S7L014ATMA1" FP-IAUCN04S7L014ATMA1_TDSON8-MFG 2772,1167 r270 top
Q4 "IAUCN04S7L014ATMA1" FP-IAUCN04S7L014ATMA1_TDSON8-MFG 3114,1494 r270 top
Q4A "IAUCN04S7L014ATMA1" FP-IAUCN04S7L014ATMA1_TDSON8-MFG 3114,1167 r270 top
Q5 "SI7155DP-T1-GE3" FP-SI7155DP-T1-GE3_PowerPAK-SO8-MFG 950.97,1590.67 r180 top
Q6 "CSD18540Q5B" DNK0008A 1076.06,1582.5 r0 bottom value=60V
Q7 "BC807-40LT1G" SOT-23 4657.64,2588.22 r0 bottom value="45 V"
Q8 "2N7002W-7-F" SOT-323 4072.59,2098.41 r90 bottom value=60V
R1 "KRL2012E-M-R004-F-T5" FP-KRL2012E-M-R004-F-T5_2012-MFG 1290,1435 r0 top value=4m
R2 "KRL2012E-M-R004-F-T5" FP-KRL2012E-M-R004-F-T5_2012-MFG 1290,1535 r0 top value=4m
R3 "KRL2012E-M-R003-F-T5" FP-KRL2012E-M-R003-F-T5_0805-MFG 2376,864.04 r270 top value=3m
R4 "KRL2012E-M-R003-F-T5" FP-KRL2012E-M-R003-F-T5_0805-MFG 2270,864.04 r270 top value=3m
R5 "RMCF0603ZT0R00" 0603S 2288.38,1747 r180 top value=0
R6 "RMCF0603ZT0R00" 0603S 2144.38,1800 r180 top value=0
R7 "CRCW060310R0FKEAHP" 0603S 2140,1670 r180 top value=10.0
R8 "CRCW060310R0FKEAHP" 0603S 2138.96,1724.18 r180 top value=10.0
R9 "RC0603FR-0782KL" 0603S 2071.17,1780.32 r270 top value=82.0k
R10 "CRCW06037K32FKEA" 0603S 2017.44,1841.01 r270 top value=7.32k
R11 "RMCF0603ZT0R00" 0603S 2239.9,1641.02 r180 top value=0
R12 "RMCF0603ZT0R00" 0603S 2500,1634.1 r180 top value=0
R13 "MCT06030C2008FP500" 0603S 2665,1350 r0 top value=2.00
R14 "RMCF0603ZT0R00" 0603S 2980.59,1351.86 r0 top value=0
R15 "RC0603FR-0775KL" 0603S 930.36,2832.68 r180 top value=75.0k
R16 "RMCF0603ZT0R00" 0603S 1000,2870 r90 top value=0
R17 "CRCW060319K6FKEA" 0603S 1070.61,2832.68 r180 top value=19.6k
R18 "RMCF0603ZT0R00" 0603S 2100.43,2029.98 r90 top value=0
R19 "RC0603FR-0710RL" 0603S 2070.79,1885.58 r270 top value=10.0
R20 "RC0603FR-0782KL" 0603S 2266.51,1970.42 r270 top value=82.0k
R21 "CRCW06037K32FKEA" 0603S 2320.21,1970.86 r90 top value=7.32k
R22 "RMCF0603ZT0R00" 0603S 2638.15,2196.57 r270 top value=0
R23 "RMCF0603ZT0R00" 0603S 2756.28,2098.72 r270 top value=0
R24 "RMCF0603ZT0R00" 0603S 2647.23,2090.8 r270 top value=0
R25 "RMCF0603ZT0R00" 0603S 2470.26,2195.75 r90 top value=0
R26 "RT0603BRD0723K4L" 0603S 2076.66,2355.82 r180 top value=23.4k
R27 "RC0603FR-078K25L" 0603S 2032.57,2670.73 r90 top value=8.25k
R28 "CRCW06033K83FKEA" 0603S 2269.93,2670.85 r90 top value=3.83k
R29 "RC0603FR-078K25L" 0603S 2531.4,2196.52 r270 top value=8.25k
R30 "CRCW060378K7FKEA" 0603S 2417.36,2195.75 r270 top value=78.7k
R31 "RT0603BRD0750K5L" 0603S 2470.26,2098.72 r270 top value=50.5k
R32 "CRCW060310K5FKEA" 0603S 2332.19,2042.59 r0 top value=10.5k
R33 "RT0603BRD0710KL" 0603S 2918.51,2793.22 r180 top value=10.0k
R34 "RMCF0603ZT0R00" 0603S 2800.28,1811.92 r270 top value=0
R35 "RMCF0603ZT0R00" 0603S 2144.38,1852.68 r180 top value=0
R36 "RMCF0603ZT0R00" 0603S 2985,1015 r0 top value=0
R37 "RMCF0603ZT0R00" 0603S 1400,2853.75 r90 top value=0
R38 "CRCW060343K0JNEA" 0603S 1079,1728 r0 top value=43k
R39 "CRCW0603180KJNEA" 0603S 1115.29,1650 r270 top value=180k
R40 "CRCW0603511RFKEA" 0603S 3621,2700 r270 top value=511
R41 "CRCW06031K15FKEA" 0603S 3568,2700 r270 top value=1.15k
R42 "RC0603FR-071K87L" 0603S 3515,2700 r270 top value=1.87k
R43 "RC0603FR-072K7L" 0603S 3462,2700 r270 top value=2.70k
R44 "CRCW06033K83FKEA" 0603S 3409,2700 r270 top value=3.83k
R45 "RC0603FR-075K1L" 0603S 3356,2700 r270 top value=5.10k
R46 "RC0603FR-076K49L" 0603S 3303.61,2700.47 r270 top value=6.49k
R47 "RC0603FR-078K25L" 0603S 4174,2700 r270 top value=8.25k
R48 "CRCW060310K5FKEA" 0603S 4121,2700 r270 top value=10.5k
R49 "RC0603FR-0713K3L" 0603S 4068,2700 r270 top value=13.3k
R50 "CRCW060316K2FKEA" 0603S 4015,2700 r270 top value=16.2k
R51 "RC0603FR-0720K5L" 0603S 3962,2700 r270 top value=20.5k
R52 "CRCW060324K9FKEA" 0603S 3909,2700 r270 top value=24.9k
R53 "CRCW060330K1FKEA" 0603S 3856,2700 r270 top value=30.1k
R54 "CRCW060335K7FKEA" 0603S 3803,2700 r270 top value=35.7k
R55 "CRCW06032K70JNEA" 0603S 2531.4,2090.8 r270 top value=2.7k
R56 "RMCF0603ZT0R00" 0603S 2347.75,1864.12 r270 top value=0
R57 "RMCF0603ZT0R00" 0603S 1400,2760 r270 top value=0
R58 "RC0603FR-075K1L" 0603S 888.6,1661.7 r270 bottom value=5.10k
R59 "CRCW06033R00JNEA" 0603S 2410,1600 r180 bottom value=3.0
R60 "CRCW06033R00JNEA" 0603S 2745,1645 r0 bottom locked value=3.0
R61 "RMCF0603ZT0R00" 0603S 2190,1350 r180 top value=0
R62 "RMCF0603ZT0R00" 0603S 2510,1350 r180 top value=0
R63 "MCT06030C2008FP500" 0603S 2640,1015 r0 top value=2.00
R64 "RC0603FR-072KL" 0603S 2097.58,2670.79 r270 top value=2.00k
R65 "RC0603FR-072KL" 0603S 2200.92,2670.85 r270 top value=2.00k
R66 "RMCF0603ZT0R00" 0603S 3750.01,2495.58 r180 bottom value=0
R67 "RMCF0603ZT0R00" 0603S 3750.01,2438.95 r180 bottom value=0
R68 "RMCF0603ZT0R00" 0603S 2438,2195 r180 bottom value=0
R69 "RC0603FR-07100KL" 0603S 4769.74,2477 r0 bottom value=100k
R70 "RC0603FR-074K7L" 0603S 4770,2420 r180 bottom value=4.70k
R71 "CRCW060310K0FKEA" 0603S 4495.53,2626 r0 bottom value=10.0k
R72 "RC0603FR-0710RL" 0603S 4505.53,2477 r180 bottom value=10.0
R73 "CRCW060310K0FKEA" 0603S 4505.53,2550.81 r180 bottom value=10.0k
R74 "CRCW060310K0FKEA" 0603S 3750.01,2555 r180 bottom value=10.0k
R75 "RMCF0603ZT0R00" 0603S 3844.53,2437.5 r0 bottom value=0
R76 "RC0603FR-0710RL" 0603S 4593.66,2689.74 r0 bottom value=10.0
R77 "RC0603FR-0747K5L" 0603S 3619.66,1890.5 r270 bottom value=47.5k
R78 "RC0603FR-0747K5L" 0603S 3535.68,1889.01 r270 bottom value=47.5k
R79 "RC0603FR-0747K5L" 0603S 3683.97,1891.54 r270 bottom value=47.5k
R80 "RC0603FR-072K15L" 0603S 3568.03,1994.5 r270 bottom value=2.15k
R81 "RC0603JR-071KL" 0603S 3622.03,1994 r90 bottom value=1.0k
R82 "RC0603JR-071KL" 0603S 3648.53,2135.5 r0 bottom value=1.0k
R83 "CRCW060310K0FKEA" 0603S 3833.8,2252.71 r180 bottom value=10.0k
R84 "RC0603FR-07150KL" 0603S 3743.14,2192.2 r0 bottom value=150k
R85 "RMCF0603ZT0R00" 0603S 3949.16,2134.51 r180 bottom value=0
R86 "RT0603BRD0710KL" 0603S 3947.68,2061.01 r0 bottom value=10.0k
R87 "RT0603BRD0710KL" 0603S 3949.16,1994.11 r0 bottom value=10.0k
R88 "RC0603FR-073K32L" 0603S 4220.18,2351.51 r180 bottom value=3.32k
R89 "RT0603BRD0710KL" 0603S 4300.18,2250.51 r270 bottom value=10.0k
R90 "RT0603BRD0710KL" 0603S 4569.18,2333.01 r270 bottom value=10.0k
R91 "RMCF0603ZT0R00" 0603S 4210.18,2282.99 r0 bottom value=0
R92 "RC0603FR-0747K5L" 0603S 3441.84,2263.59 r270 bottom value=47.5k
R93 "RC0603FR-0747K5L" 0603S 3564.83,2266.56 r270 bottom value=47.5k
R94 "RC0603FR-0747K5L" 0603S 3503.34,2265.08 r270 bottom value=47.5k
R95 "RC0603FR-072K15L" 0603S 3478.03,2338 r0 bottom value=2.15k
R96 "RC0603JR-071KL" 0603S 3432.03,2452.5 r90 bottom value=1.0k
R97 "RC0603JR-071KL" 0603S 3370.03,2452 r90 bottom value=1.0k
R98 "CRCW060310K0FKEA" 0603S 3618.52,2589.8 r180 bottom value=10.0k
R99 "RC0603FR-07150KL" 0603S 3563.35,2651.3 r0 bottom value=150k
R100 "ST-5ETW103" FP-ST-5ETW103_SMT3_6MM0_4MM3-MFG 4437.2,2074.07 r270 bottom value=10kΩ
S1 "218-8LPST" SW_218-8LP 3490,2425 r270 top
S2 "218-8LPST" SW_218-8LP 3990,2425 r270 top
SH-JP1 "M7582-05" Harwin_M7582-05 3592.48,3000 r0 top
SH-JP2 "M7582-05" Harwin_M7582-05 4497.59,3000 r0 top
SH-JP3 "M7582-05" Harwin_M7582-05 4101,3000 r0 top
SH-JP4 "M7582-05" Harwin_M7582-05 200,2505.33 r180 top
SH-JP5 "M7582-05" Harwin_M7582-05 949.87,3000 r180 top
SH-JP6 "M7582-05" Harwin_M7582-05 1754.31,2151.71 r90 top
SH-JP7 "M7582-05" Harwin_M7582-05 1348.99,3000 r180 top
SH-JP8 "M7582-05" Harwin_M7582-05 2499.6,2439.7 r90 top
SH-JP9 "M7582-05" Harwin_M7582-05 1748.72,3000 r180 top
SH-JP10 "M7582-05" Harwin_M7582-05 2032.75,2454.32 r0 top
SH-JP11 "M7582-05" Harwin_M7582-05 1910.32,2650.3 r90 top
SH-JP12 "M7582-05" Harwin_M7582-05 2399.76,2650.3 r90 top
TP1 "5010" Keystone5010 380,1330 r180 top locked
TP2 "5010" Keystone5010 5073.68,1347.36 r0 top
TP3 "5011" Keystone5011 380,850 r0 top
TP4 "5011" Keystone5011 5073.68,839.75 r0 top
TP5 "S2761-46R" Harwin_S2761-46R 2322.86,995 r0 top
TP6 "S2761-46R" Harwin_S2761-46R 2859,995 r0 top
TP7 "5013" Keystone5013 1200,1835 r0 top
TP8 "5013" Keystone5013 1380,1835 r180 top
TP9 "5001" Keystone5001 3038,2310 r90 top
TP10 "5004" Keystone5004 1700,2450.86 r90 top
TP11 "5004" Keystone5004 2870.29,2219.44 r270 top
TP12 "5004" Keystone5004 3038,2200 r270 top
TP13 "5004" Keystone5004 2333.66,2205.39 r0 top
TP14 "5001" Keystone5001 2223.66,2205.39 r0 top
TP15 "5004" Keystone5004 3038,1927.91 r90 top
U1 "LM51772RHARQ1" RHA0040P-MFG 2553,1833 r270 top
U2 "TLV431IDBZR" DBZ0003A_N 4647.81,2433.14 r180 bottom
U3 "TLV9030DCKR" DCK0005A-MFG 3749.18,2031.51 r0 bottom
U4 "TLV431IDBZR" DBZ0003A_N 4429.53,2272.5 r0 bottom
U5 "OPA310IDCKR" DCK0005A-MFG 3583.03,2457.79 r0 bottom
ZZ2 "These assemblies are ESD sensitive, ESD precautions shall be observed." AssemblyNote 0,3500 r0 top
ZZ3 "These assemblies must be clean and free from flux and all contaminants. Use of no clean flux is not acceptable." AssemblyNote 0,3400 r0 top
ZZ4 "These assemblies must comply with workmanship standards IPC-A-610 Class 2, unless otherwise specified." AssemblyNote 0,3300 r0 top

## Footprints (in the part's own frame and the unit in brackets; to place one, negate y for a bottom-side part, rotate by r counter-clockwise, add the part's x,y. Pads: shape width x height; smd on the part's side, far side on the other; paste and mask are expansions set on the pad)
0402S [mil] "Based on C0402S footprint from PADS legacy"
  rect 15x24 smd: 1(-20,0) 2(20,0)
  body extent -22,-12 22,12, height 24
0603S [mil]
  rect 20x35 smd: 1(-30,0) 2(30,0)
  body extent -34,-19 34,19, height 39
0805_HV1 [mm] "Custom footprint based on analyzing multiple manufacturer recommendations"
  rrect10% 1x1.25 smd: 1(-1,0) 2(1,0)
  silkscreen extent -0.2,-0.75 0.2,0.75, body extent -1.1,-0.72 1.1,0.73, height 1.45
1210L [mm] "1210 from SM-752 data"
  rect 1.1x2.6 smd: 1(-1.35,0) 2(1.35,0)
  silkscreen extent -0.4,-1.2 0.4,1.2, body extent -1.7,-1.35 1.7,1.35, height 1.35
AssemblyNote [mil] "Assembly Note"
CONN_2510-6002 [mm] "3M 2500 series TS-0770-L December 15, 2011"
  rect 1.65x1.65 hole 1.016 mask+0: 1(-5.08,-1.27)
  round 1.65 hole 1.016 mask+0: 2(-5.08,1.27) 3(-2.54,-1.27) 4(-2.54,1.27) 5(0,-1.27) 6(0,1.27) 7(2.54,-1.27) 8(2.54,1.27) 9(5.08,-1.27) 10(5.08,1.27)
  silkscreen extent -10.01,-4.17 10.01,4.47, body extent -10.01,-4.11 10.01,4.52, height 9.92
DBZ0003A_N [mm] "SOT23, 3-Leads, Body 2.9x1.3mm, Pitch 0.95mm, Lead Span 2.4mm, IPC Medium Density"
  rrect17% 1x0.6 smd: 1(-1.2,0.95) 2(-1.2,-0.95) 3(1.2,0)
  silkscreen extent 0.2,-1.5 0.7,1.5, body extent -1.26,-1.46 1.26,1.46, height 0.98
DCK0005A-MFG [mm]
  rrect25% 0.95x0.4 smd paste+0 mask+0: 1(-1.1,0.65) 2(-1.1,0) 3(-1.1,-0.65) 4(1.1,-0.65) 5(1.1,0.65)
  silkscreen extent -2.25,-1.07 0.23,1.07, body extent -1.05,-1 1.05,1, height 1.1
DNK0008A [mm] "SON, 8-Leads, Body 5x6mm"
  rrect39% 0.86x0.51 smd paste-0.05 mask-0.05: 1(-2.82,1.905) 2(-2.82,0.635) 3(-2.82,-0.635) 4(-2.82,-1.905) 5(2.82,-1.905) 6(2.82,-0.635) 7(2.82,0.635) 8(2.82,1.905)
  rrect40% 0.25x0.555 on Bottom Paste: 9(-0.83,-2.372) 9(-0.83,2.372)
  rrect40% 0.25x0.555 on Bottom Solder: 9(-0.83,-2.372) 9(-0.83,2.372)
  rrect11% 0.95x1.13 on Bottom Paste: 9(-0.535,-1.33) 9(-0.535,0) 9(-0.535,1.33) 9(0.615,-1.33) 9(0.615,0) 9(0.615,1.33) 9(1.765,-1.33) 9(1.765,0) 9(1.765,1.33)
  rrect3% 3.58x4 on Bottom Solder: 9(0.75,0)
  rrect5% 4.34x5.4 smd paste-3 mask-3: 9(1.08,0)
  body extent -3.05,-2.55 3.05,2.55, height 1.06
FCC_disclaimer [mil]
Fiducial10-20 [mm]
  round 1 smd mask+0.5: 1(0,0)
  Top Layer keep-out circle w1.178: c0,0 r0.5
FP-A768KE276M1JLAE054_SMT_CAP_8MM3_8MM3-0 [mm]
  rrect5% 4.2x2.2 smd paste+0 mask+0: 1(-3.65,0) 2(3.65,0)
  silkscreen extent -6.42,-4.25 4.25,4.25, body extent -6,-4.5 6,4.5, height 0.25
FP-A768MS127M1HLAE024_SMT_CAP_10MM3_10MM3-MFG [mm]
  rrect5% 4.4x2.2 smd paste+0 mask+0: 1(-4.45,0) 2(4.45,0)
  silkscreen extent -7.32,-5.25 5.25,5.25, body extent -6.9,-5.5 6.9,5.5, height 0.25
FP-BAS70-04-E3-18_SOT23-3-MFG [mm]
  rrect14% 0.9x0.7 smd paste+0 mask+0: 1(-1,0.95) 2(-1,-0.95) 3(1,0)
  silkscreen extent -0.71,-1.55 0.71,1.55, body extent -1.24,-1.48 1.24,1.48, height 1.15
FP-C3225X7R2A106K250AC_1210-MFG [mm]
  rrect9% 1.1x2.2 smd paste+0 mask+0: 1(-1.65,0) 2(1.65,0)
  silkscreen extent -0.72,-1.43 0.72,1.43, body extent -2.3,-1.53 2.3,1.53, height 0.25
FP-GCM188L81H104KA57D_0603-MFG [mm]
  rrect15% 0.65x0.7 smd paste+0 mask+0: 1(-0.675,0) 2(0.675,0)
  body extent -1.1,-0.55 1.1,0.55, height 0.25
FP-IAUCN04S7L014ATMA1_TDSON8-MFG [mm] "Recommended Land Pattern"
  rrect7% 3.14x1.5 smd paste-1000 mask-1000: 1-2-3(-0.635,-3.02)
  rrect17% 0.6x1.5 smd paste-1000 mask+0: 4(1.905,-3.02)
  rrect2% 4.41x4.9 smd paste-1000 mask-1000: 5-6-7-8(0,1.32)
  silkscreen extent -2.63,-4.47 2.63,2.79, body extent -2.96,-3.87 2.96,3.87, height 0.25
FP-KRL2012E-M-R003-F-T5_0805-MFG [mm]
  rrect14% 0.7x2.2 smd paste+0 mask+0: 1(-0.65,0) 2(0.65,0)
  silkscreen extent -0.72,1.5 0.72,1.5, body extent -1.1,-1.2 1.1,1.2, height 0.25
FP-KRL2012E-M-R004-F-T5_2012-MFG [mm]
  rrect14% 0.7x2.2 smd paste+0 mask+0: 1(-0.65,0) 2(0.65,0)
  silkscreen extent -0.77,-1.53 0.67,-1.53, body extent -1.1,-1.2 1.1,1.2, height 0.25
FP-SI7155DP-T1-GE3_PowerPAK-SO8-MFG [mil]
  rrect16% 50x24 smd paste+0 mask+0: 1(-105,75) 2(-105,25) 3(-105,-25) 4(-105,-75)
  round 132.13 smd paste+0 mask+0: 5-6-7-8(25.41,2.72)
  Top Layer region: -48,77 90,77 90,87 130,87 130,63 102,63 102,37 130,37 130,13 102,13 102,-13 130,-13 130,-37 102,-37 102,-63 130,-63 130,-87 90,-87 90,-77 -48,-77
  silkscreen extent -157,-110 118,110, body extent -120,-102 122,101, height 46
FP-ST-5ETW103_SMT3_6MM0_4MM3-MFG [mm]
  rrect7% 1.4x2 smd paste+0 mask+0: 1(-2.5,-2.65) 2(0,2.65) 3(2.5,-2.65)
  silkscreen extent -3.15,-4.33 3.15,2.3, body extent -3,-3.15 3,3.15, height 8.35
Harwin_M7582-05 [mil] "Single Operation 2.54mm Pitch Open Top Jumper Socket"
  body extent -98,-47 98,47, height 236
Harwin_S2761-46R [mm] "Natural PC Test Point Brass, SMT"
  rrect10% 1.8x1 smd: 1(0,0)
  body extent -0.8,-0.4 0.8,0.4, height 1.15
IEC_HotSurface_Small [mil]
  silkscreen extent -107,-93 107,92
Johnson_108-0740-001 [mm] "Banana Jack Uninsulated Standard Type"
  round 12 hole 6.858: 1(0,0)
  body extent -4.77,-5.43 4.75,5.57, height 2.39
Keystone5001 [mil] "For Keystone 500x miniature loop terminals"
  round 80 hole 40: 1(0,0)
  silkscreen extent -52,-52 52,52, body extent -49,-49 49,49, height 182
Keystone5004 [mil] "For Keystone 500x miniature loop terminals"
  round 80 hole 40: 1(0,0)
  silkscreen extent -52,-52 52,52, body extent -49,-49 49,49, height 182
Keystone5010 [mil] "Keystone Multipurpose loops"
  round 87 hole 63: 1(0,0)
  silkscreen extent -70,-70 70,70, body extent -63,-63 63,62, height 319
Keystone5011 [mil] "Keystone Multipurpose loops"
  round 87 hole 63: 1(0,0)
  silkscreen extent -70,-70 70,70, body extent -63,-63 63,62, height 319
Keystone5013 [mil] "Keystone Multipurpose loops"
  round 87 hole 63: 1(0,0)
  silkscreen extent -70,-70 70,70, body extent -63,-63 63,62, height 319
Keystone_1902C [mil] "Hex Standoff, 4-40 threaded, nylon"
  round 1 on Mech4: 0(0,0)
  body extent -145,-126 146,126, height 501
Net-Tie_10mil [mil] "10mil net tie, no solder mask opening, no solder paste"
  rect 10x10 smd paste-5 mask-5: 1(-10,0) 2(10,0)
  Top Layer region: -6,5 6,5 6,-5 -6,-5
"NY PMS 440 0025 PH" [mm] "4-40 nylon screw and mounting hole"
  round 8 hole 3.2: 1(0,0)
  body extent -3.3,-3.3 3.3,3.3, height 2.69
RHA0040P-MFG [mm] "Recommended Land Pattern"
  rrect40% 0.6x0.25 smd paste+0 mask+0: 1(-2.9,2.25) 2(-2.9,1.75) 3(-2.9,1.25) 4(-2.9,0.75) 5(-2.9,0.25) 6(-2.9,-0.25) 7(-2.9,-0.75) 8(-2.9,-1.25) 9(-2.9,-1.75) 10(-2.9,-2.25) 21(2.9,-2.25) 22(2.9,-1.75) 23(2.9,-1.25) 24(2.9,-0.75) 25(2.9,-0.25) 26(2.9,0.25) 27(2.9,0.75) 28(2.9,1.25) 29(2.9,1.75) 30(2.9,2.25)
  rrect40% 0.25x0.6 smd paste+0 mask+0: 11(-2.25,-2.9) 12(-1.75,-2.9) 13(-1.25,-2.9) 14(-0.75,-2.9) 15(-0.25,-2.9) 16(0.25,-2.9) 17(0.75,-2.9) 18(1.25,-2.9) 19(1.75,-2.9) 20(2.25,-2.9) 31(2.25,2.9) 32(1.75,2.9) 33(1.25,2.9) 34(0.75,2.9) 35(0.25,2.9) 36(-0.25,2.9) 37(-0.75,2.9) 38(-1.25,2.9) 39(-1.75,2.9) 40(-2.25,2.9)
  rrect3% 3.3x3.3 smd paste-1000 mask+0: 41(0,0)
  silkscreen extent -3.87,-3.05 3.05,3.05, body extent -3.3,-3.3 3.3,3.3, height 0.25
Samtec_HTSW-103-07-x-D [mm] "Header, 2.54mm, 3x2, Gold, TH"
  rrect50% 1.55x1.55 hole 1.02: 1(-1.27,2.54)
  round 1.55 hole 1.02: 2(1.27,2.54) 3(-1.27,0) 4(1.27,0) 5(-1.27,-2.54) 6(1.27,-2.54)
  silkscreen extent -2.61,-3.91 2.61,4.3, body extent -2.51,-3.81 2.51,3.81, height 8.38
SOD-123 [mm] "On Semi recommended land pattern"
  rect 0.915x1.22 smd: 1(-1.637,0) 2(1.637,0)
  silkscreen extent -2.79,-1.17 2.03,1.17, body extent -1.93,-0.9 1.93,0.9, height 1.35
SOT-23 [mm] "SOT23, 3-Leads, Body 2.9x1.3mm, Pitch 0.95mm, Lead Span 2.5mm, IPC Medium Density"
  rrect50% 1x0.6 smd: 1(-1.2,0.95) 2(-1.2,-0.95) 3(1.2,0)
  silkscreen extent -1.63,-1.5 0.7,1.5, body extent -1.16,-1.45 1.21,1.45, height 1
SOT-323 [mm] "Diodes Inc recommended land pattern.  2016-02-24"
  rrect21% 0.6x0.47 smd: 1(-0.95,0.65) 2(-0.95,-0.65) 3(0.95,0)
  silkscreen extent -1.14,-1.22 0.77,1.22, body extent -1.13,-1.13 1.12,1.12, height 1.13
SW_218-8LP [mm] "SMD, 16-Leads, Body 11.33x5.8mm, Pitch 1.27mm"
  rect 1.27x0.76 smd: 1(-3.81,4.445) 2(-3.81,3.175) 3(-3.81,1.905) 4(-3.81,0.635) 5(-3.81,-0.635) 6(-3.81,-1.905) 7(-3.81,-3.175) 8(-3.81,-4.445) 9(3.81,-4.445) 10(3.81,-3.175) 11(3.81,-1.905) 12(3.81,-0.635) 13(3.81,0.635) 14(3.81,1.905) 15(3.81,3.175) 16(3.81,4.445)
  silkscreen extent -2.9,-5.67 2.9,5.9, body extent -4.22,-5.66 4.22,5.66, height 2.62
WE-HCB_1890 [mm] "WURTH ELEKTRONIK"
  rect 6x6 smd: 1(-6.65,0) 2(6.65,0)
  silkscreen extent -9.7,-9.4 9.7,9.4, body extent -9.65,-9.35 9.65,9.35, height 9.2
WEEE_Minimum [mil] "WEEElie bin"
  silkscreen extent -95,-172 99,104
WURTH_61300211121 [mm] "Header, 2.54mm, 2x1, TH"
  rrect50% 1.65x1.65 hole 1.15: 1(-1.27,0)
  round 1.65 hole 1.15: 2(1.27,0)
  body extent -2.54,-1.27 2.54,1.27, height 8.54
WURTH_61300311121 [mm] "Header, 2.54mm, 3x1, TH"
  rrect50% 1.65x1.65 hole 1.15: 1(-2.54,0)
  round 1.65 hole 1.15: 2(0,0) 3(2.54,0)
  body extent -3.81,-1.27 3.81,1.27, height 8.54
Wurth_61300511121 [mm] "Header, 2.54mm, 5x1, TH"
  rrect50% 1.65x1.65 hole 1.1: 1(-5.08,0)
  round 1.65 hole 1.1: 2(-2.54,0) 3(0,0) 4(2.54,0) 5(5.08,0)
  body extent -6.35,-1.27 6.35,1.27, height 8.54
WURTH_61300611121 [mm] "Header, 2.54mm, 6x1, TH"
  rrect50% 1.65x1.65 hole 1.15: 1(-6.35,0)
  round 1.65 hole 1.15: 2(-3.81,0) 3(-1.27,0) 4(1.27,0) 5(3.81,0) 6(6.35,0)
  body extent -7.62,-1.27 7.62,1.27, height 8.54

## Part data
C1 C25 C26: library part CMP-0097690-1, "Cap Aluminum Polymer 27uF 63V 20% Solder Cylindrical 54m Ohm 1175mA 2000 hr 125°C T/R", Digikey Part Number=399-A768KE276M1JLAE054CT-ND, Leakage Current=340uA, Manufacturer=KEMET, Mouser Part Number=80-A768KE276M1JLAE54, Operating Temperature Range="-55°C to +125°C", Tolerance_%=20%, ValueDisplayed=27uF
C2 C3 C4 C5 C6 C30 C32 C65 C66 C67 C68: library part CMP-0096021-1, "10 µF ±10% 100V Ceramic Capacitor X7R 1210 (3225 Metric)", Digikey Part Number=445-C3225X7R2A106K250ACCT-ND, Manufacturer=TDK, Mouser Part Number=810-C3225X7R2A106K25, Operating Temperature Range="-55°C to +125°C", TempCo=15%, Temperature Characteristic=X7R, Tolerance_%=10%, ValueDisplayed=10uF
C7 C8 C9 C10 C21 C22 C23 C24 C31 C69 C70 C71 C72 C83 C84 C85 C86 C87 C88: library part CMP-0064935-4, "CAP, CERM, 0.1 uF, 100 V,+/- 10%, X7R, AEC-Q200 Grade 1, 0603", Cap_Case=0603, Manufacturer=MuRata, Supplier Part Number 1=490-13420-1-ND, TempCo=X7R, Tolerance_%=10%, Value1=Unknown, Value2=100V, ValueDisplayed=0.1uF
C11 C12 C13 C14 C15 C16 C17 C18 C19 C20 C73 C74 C75 C76 C77 C78 C79 C80 C81 C82: library part CMP-0085817-1, "CAP, CERM, 22 µF, 35 V,+/- 20%, X5R, 1210", Cap_Case=1210, Manufacturer="Taiyo Yuden", TempCo=X5R, Tolerance_%=20%, Value2=35V, ValueDisplayed=22µF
